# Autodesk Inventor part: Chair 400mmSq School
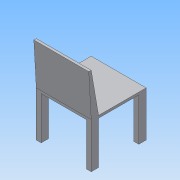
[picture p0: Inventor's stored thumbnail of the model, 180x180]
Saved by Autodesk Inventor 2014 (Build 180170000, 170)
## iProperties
Created: 2013-05
Part Number: Chair 400mmSq School
Material: Generic
Document SubType Name: Modeling
Designer: john.everitt
Mass: 13710 g
Surface Area: 10485.5 cm^2
Volume: 13710 cm^3
Density: 1 g/cm^3
Appearance: Default
Author: john.everitt
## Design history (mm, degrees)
sketch "Sketch1"
  geometry: L1 (0, 0)-(450, 0); L2 (450, 0)-(450, 450); L3 (450, 450)-(0, 450); L4 (0, 450)-(0, 0); L5 (0, 0)-(40, 0); L6 (40, 0)-(40, 60); L7 (40, 60)-(0, 60); L8 (0, 60)-(0, 0); L9 (0, 450)-(40, 450); L10 (40, 450)-(40, 390); L11 (40, 390)-(0, 390); L12 (0, 390)-(0, 450); L13 (450, 450)-(410, 450); L14 (410, 450)-(410, 390); L15 (410, 390)-(450, 390); L16 (450, 390)-(450, 450); L17 (450, 0)-(410, 0); L18 (410, 0)-(410, 60); L19 (410, 60)-(450, 60); L20 (450, 60)-(450, 0)
  constraints: 40 end point, 10 parallel, 6 equal length, 5 horizontal, 5 perpendicular
  dimensions: "d0" = 450 distance between parallel lines of L3 L1; "d1" = 450 distance between parallel lines of L2 L4; "d2" = 60 distance between parallel lines of L7 L1; "d3" = 40 distance between parallel lines of L6 L4
extrude "Extrusion1" new body sketch "Sketch1" distance "d4" = 350; taper "d5" = 0 deg
sketch "Sketch2"
  geometry: L1 (450, 450)-(410, 450) reference; L2 (410, 450)-(410, 390) reference; L3 (410, 390)-(450, 390) reference; L4 (450, 390)-(450, 450) reference; L5 (0, 0)-(450, 0); L6 (450, 0)-(450, 450); L7 (450, 450)-(0, 450); L8 (0, 450)-(0, 0)
  constraints: 8 end point, 2 parallel, 1 horizontal, 1 perpendicular
extrude "Extrusion2" join sketch "Sketch2" distance "d6" = 20; taper "d7" = 0 deg
sketch "Sketch3"
  geometry: L1 (370, 450)-(370, 0) reference; L2 (370, 60)-(370, 0); L3 (720, -20)-(720, 0); L4 (720, 0)-(370, 60); L5 (370, 0)-(720, -20); L6 (0, 0)-(370, 0) reference
  constraints: 8 end point, 2 point on line, 1 collinear, 1 parallel
  dimensions: "d8" = 60 distance of L2.start L1.end; "d9" = 350 distance between parallel lines of L3 L1; "d10" = 20 distance of L3.start L3.end
extrude "Extrusion3" join sketch "Sketch3" stored distance "d11" = 0; taper "d12" = 0 deg
body "Solid1"
node "Projected Loop1"
